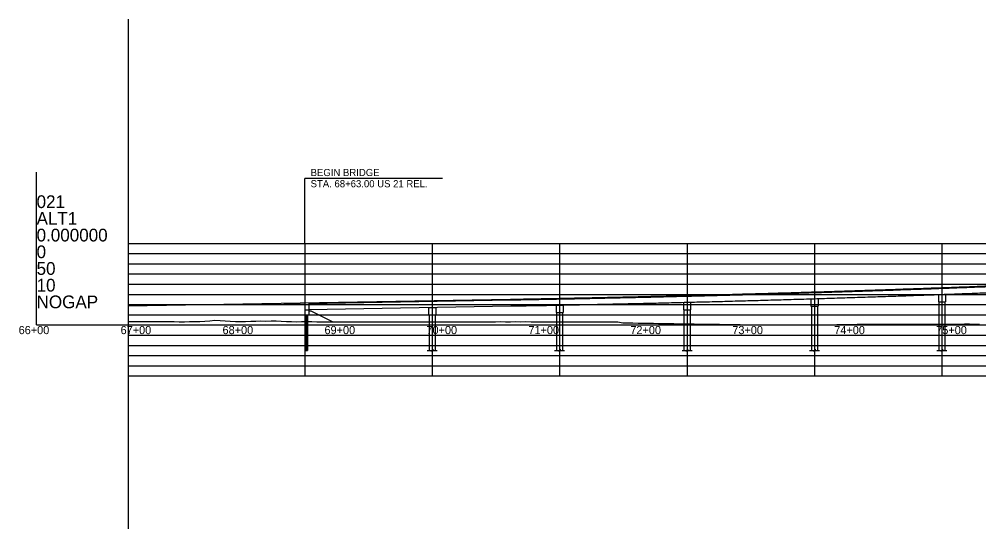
# Model space of a CAD drawing. Extents: x -464 to 4306, y -1372 to 300.
# Drawn here: x -187 to 754, y -200 to 300 of the extents above; entities that cross this region are included whole.
import ezdxf

# ---------------------------------------------------------------- set-up
doc = ezdxf.new("R2010")
doc.units = 0
for name, color, linetype in [('BR_AUTO DIMENSION', 7, 'Continuous'), ('BR_GRID LINES', 7, 'Continuous'), ('Default', 7, 'Continuous'), ('Mis Ground Lines', 7, 'Continuous'), ('Miscellaneous Lines', 7, 'Continuous'), ('NOPLOT', 7, 'Continuous'), ('sub interior bent cap lines', 7, 'Continuous'), ('Sub Interior Bent Footing Line', 7, 'Continuous'), ('Sub Steel Pile Lines', 7, 'Continuous'), ('Sup Concrete Girder Lines', 7, 'Continuous'), ('Sup Concrete Slab Lines', 7, 'Continuous')]:
    doc.layers.add(name, color=color, linetype=linetype)

msp = doc.modelspace()

# ---------------------------------------------------------------- linework, layer by layer
at = {"layer": 'BR_AUTO DIMENSION'}
for points in [[(93.81, -25), (94.51, -25), (94.51, -25.32), (94.83, -24.68), (94.83, -25), (95.53, -25)], [(212.8, -25), (217.11, -25), (217.11, -26.12), (218.23, -23.88), (218.23, -25), (222.55, -25)], [(337.8, -25), (342.11, -25), (342.11, -26.12), (343.23, -23.88), (343.23, -25), (347.55, -25)], [(462.8, -25), (467.11, -25), (467.11, -26.12), (468.23, -23.88), (468.23, -25), (472.55, -25)], [(587.8, -25), (592.11, -25), (592.11, -26.12), (593.23, -23.88), (593.23, -25), (597.55, -25)], [(712.8, -25), (717.11, -25), (717.11, -26.12), (718.23, -23.88), (718.23, -25), (722.55, -25)]]:
    msp.add_lwpolyline(points, dxfattribs=at)
at = {"layer": 'BR_GRID LINES'}
for p, q in [((-80.33, 300), (-80.33, -200)), ((-80.33, 80), (3939.67, 80)), ((-80.33, 70), (3939.67, 70)), ((-80.33, 60), (3939.67, 60)), ((-80.33, 50), (3939.67, 50)), ((-80.33, 40), (3939.67, 40)), ((-80.33, 30), (3939.67, 30)), ((-80.33, 20), (3939.67, 20)), ((-80.33, 10), (3939.67, 10)), ((-80.33, 0), (3939.67, 0)), ((-80.33, -10), (3939.67, -10)), ((-80.33, -20), (3939.67, -20)), ((-80.33, -30), (3939.67, -30)), ((-80.33, -40), (3939.67, -40)), ((-80.33, -50), (3939.67, -50))]:
    msp.add_line(p, q, dxfattribs=at)
at = {"layer": 'Default'}
for p, q in [((-170.33, 0), (-170.33, 150)), ((92.67, 80), (92.67, -50)), ((217.67, 80), (217.67, -50)), ((342.67, 80), (342.67, -50)), ((467.67, 80), (467.67, -50)), ((592.67, 80), (592.67, -50)), ((717.67, 80), (717.67, -50)), ((-170.33, 0), (4029.67, 0))]:
    msp.add_line(p, q, dxfattribs=at)
at = {"layer": 'Mis Ground Lines'}
for p, q in [((96.67, 13.81), (98.67, 13.81)), ((98.67, 13.81), (120.14, 3.08))]:
    msp.add_line(p, q, dxfattribs=at)
for points in [[(-80.33, 3.27), (-75.33, 3.48), (-70.33, 3.36)], [(-70.33, 3.36), (-65.33, 3.4), (-60.33, 3.4), (-55.33, 3.27), (-50.33, 3.54), (-45.33, 3.44), (-40.33, 3.45), (-35.33, 3.3), (-30.33, 3.21), (-25.33, 3.22), (-20.33, 3.29), (-15.33, 3.36), (-10.33, 3.53), (-5.33, 3.82), (-0.33, 4.21), (4.67, 4.56), (9.67, 4.44), (14.67, 4.05), (19.67, 3.77), (24.67, 3.53), (29.67, 3.47), (34.67, 3.49), (39.67, 3.75), (44.67, 3.69), (49.67, 3.93), (54.67, 3.85), (59.67, 3.92), (64.67, 3.93), (69.67, 3.82), (74.67, 3.52), (79.67, 3.35), (84.67, 3.13), (89.67, 3.26), (94.67, 3.36), (99.67, 3.33), (104.67, 3.19), (109.67, 3.19), (114.67, 3.15), (119.67, 3.07), (124.67, 3.11), (129.67, 3.14), (134.67, 3.07), (139.67, 3.23), (144.67, 3.17), (149.67, 3.08), (154.67, 3.1), (159.67, 3.12), (164.67, 3.11), (169.67, 3.1), (174.67, 3.1), (179.67, 3.08), (184.67, 3.07), (189.67, 3.17), (194.67, 3.12), (199.67, 3.1), (204.67, 3.11), (209.67, 3.08), (214.67, 3.11), (219.67, 3.13), (224.67, 3.09), (229.67, 3.11)], [(229.67, 3.11), (234.67, 3.14), (239.67, 3.21), (244.67, 3.19), (249.67, 3.13), (254.67, 3.12), (259.67, 3.15), (264.67, 3.19), (269.67, 3.23), (274.67, 3.21), (279.67, 3.18), (284.67, 3.27), (289.67, 3.23), (294.67, 3.22), (299.67, 3.32), (304.67, 3.18), (309.67, 3.34), (314.67, 3.1), (319.67, 3.23), (324.67, 3.2), (329.67, 3.13), (334.67, 3.15), (339.67, 3.09), (344.67, 3.08), (349.67, 3.21), (354.67, 3.22), (359.67, 3.13), (364.67, 3.07), (369.67, 3.13), (374.67, 3.12), (379.67, 3.07), (384.67, 3.18), (389.67, 3.11), (394.67, 3.16), (399.67, 3.17), (404.67, 2.05), (409.67, 2.03), (414.67, 1.95), (419.67, 1.87), (424.67, 1.79), (429.67, 1.71), (434.67, 1.63), (439.67, 1.55), (444.67, 1.48), (449.67, 1.4), (454.67, 1.32), (459.67, 1.24), (464.67, 1.16), (469.67, 1.08), (474.67, 1.01), (479.67, 0.93), (484.67, 0.85), (489.67, 0.77), (494.67, 0.69), (499.67, 0.62), (504.67, 0.54), (509.67, 0.46), (514.67, 0.38), (519.67, 0.3), (524.67, 0.23), (529.67, 0.15), (534.67, 0.16), (539.67, 0.16), (544.67, 0.17), (549.67, 0.18), (554.67, 0.16), (559.67, 0.14), (564.67, 0.12), (569.67, 0.1), (574.67, 0.13), (579.67, 0.11), (584.67, 0.09), (589.67, 0.09), (594.67, 0.07), (599.67, 0.14), (604.67, 0.21), (609.67, 0.28), (614.67, 0.35), (619.67, 0.41), (624.67, 0.48), (629.67, 0.55), (634.67, 0.62), (639.67, 0.69), (644.67, 0.76), (649.67, 0.79), (654.67, 0.79), (659.67, 0.79), (664.67, 0.78), (669.67, 0.77), (674.67, 0.76), (679.67, 0.75), (684.67, 0.72), (689.67, 0.73), (694.67, 0.74), (699.67, 0.76), (704.67, 0.75), (709.67, 0.75), (714.67, 0.79), (719.67, 0.83), (724.67, 0.87), (729.67, 0.9)], [(729.67, 0.9), (734.67, 0.94), (739.67, 0.95), (744.67, 0.95), (749.67, 0.94), (754.67, 0.93)]]:
    msp.add_lwpolyline(points, dxfattribs=at)
at = {"layer": 'Miscellaneous Lines'}
for p, q in [((72.67, 21.46), (72.67, 20.3)), ((72.67, 20.3), (92.67, 20.64))]:
    msp.add_line(p, q, dxfattribs=at)
at = {"layer": 'NOPLOT'}
for p in [(92.67, 143.85), (92.67, 80), (227.7, 143.85)]:
    msp.add_line(p, (92.67, 143.85), dxfattribs=at)
at = {"layer": 'sub interior bent cap lines'}
for p, q in [((721.17, 29.78), (714.17, 29.52)), ((714.17, 29.52), (714.17, 22.65)), ((721.17, 29.78), (721.17, 22.65)), ((346.17, 19.24), (339.17, 19.1)), ((339.17, 19.1), (339.17, 12.17)), ((346.17, 19.24), (346.17, 12.17)), ((471.17, 22.04), (464.17, 21.86)), ((464.17, 21.86), (464.17, 14.95)), ((471.17, 22.04), (471.17, 14.95)), ((596.17, 25.55), (589.17, 25.34)), ((589.17, 25.34), (589.17, 18.45)), ((596.17, 25.55), (596.17, 18.45)), ((714.17, 22.65), (721.17, 22.65)), ((714.67, 22.65), (714.67, -25)), ((720.67, 22.65), (720.67, -25)), ((214.17, 16.9), (221.17, 17.02)), ((214.17, 16.9), (214.17, 9.96)), ((214.17, 9.96), (221.17, 9.96)), ((214.67, 9.96), (214.67, -25)), ((220.67, 9.96), (220.67, -25)), ((221.17, 17.02), (221.17, 9.96)), ((339.17, 12.17), (346.17, 12.17)), ((339.67, 12.17), (339.67, -25)), ((345.67, 12.17), (345.67, -25)), ((464.17, 14.95), (471.17, 14.95)), ((464.67, 14.95), (464.67, -25)), ((470.67, 14.95), (470.67, -25)), ((589.17, 18.45), (596.17, 18.45)), ((589.67, 18.45), (589.67, -25)), ((595.67, 18.45), (595.67, -25))]:
    msp.add_line(p, q, dxfattribs=at)
at = {"layer": 'Sub Interior Bent Footing Line'}
for p, q in [((92.67, 21.81), (92.67, 9.81)), ((96.67, 21.88), (96.67, 9.81)), ((92.67, 14.81), (96.67, 14.81)), ((92.67, 9.81), (96.67, 9.81))]:
    msp.add_line(p, q, dxfattribs=at)
at = {"layer": 'Sub Steel Pile Lines'}
for p, q in [((94.06, 9.81), (94.06, -25)), ((95.28, 9.81), (95.28, -25))]:
    msp.add_line(p, q, dxfattribs=at)
at = {"layer": 'Sup Concrete Girder Lines'}
for p, q in [((96.67, 21.21), (294.68, 24.62)), ((96.67, 15.21), (294.79, 18.63))]:
    msp.add_line(p, q, dxfattribs=at)
for points in [[(294.68, 24.62), (304.68, 24.8), (314.68, 24.98), (324.68, 25.16), (334.68, 25.35), (344.68, 25.54), (354.69, 25.74), (364.69, 25.94), (374.69, 26.15), (384.69, 26.36), (394.69, 26.58), (404.69, 26.8), (414.69, 27.02), (424.69, 27.25), (434.69, 27.48), (444.69, 27.72), (454.69, 27.97), (464.69, 28.21), (474.69, 28.46), (484.69, 28.72), (494.69, 28.98), (504.69, 29.25), (514.69, 29.52), (524.69, 29.79), (534.69, 30.07), (544.69, 30.36), (554.69, 30.64), (564.69, 30.94), (574.69, 31.24), (584.69, 31.54), (594.69, 31.84), (604.69, 32.16), (614.69, 32.47), (624.69, 32.79), (634.69, 33.12), (644.69, 33.45), (654.69, 33.78), (664.69, 34.12), (674.69, 34.46), (684.7, 34.81), (694.7, 35.16), (704.7, 35.52), (714.7, 35.88), (724.7, 36.25), (734.7, 36.62), (744.7, 36.99), (754.7, 37.37), (764.7, 37.75), (774.7, 38.14), (784.7, 38.54), (794.7, 38.93)], [(294.79, 18.63), (304.79, 18.8), (314.79, 18.98), (324.8, 19.16), (334.8, 19.35), (344.8, 19.54), (354.8, 19.74), (364.81, 19.94), (374.81, 20.15), (384.81, 20.36), (394.82, 20.58), (404.82, 20.8), (414.82, 21.02), (424.83, 21.25), (434.83, 21.49), (444.83, 21.72), (454.84, 21.97), (464.84, 22.21), (474.84, 22.47), (484.84, 22.72), (494.85, 22.98), (504.85, 23.25), (514.85, 23.52), (524.86, 23.8), (534.86, 24.07), (544.86, 24.36), (554.87, 24.65), (564.87, 24.94), (574.87, 25.24), (584.87, 25.54), (594.88, 25.85), (604.88, 26.16), (614.88, 26.47), (624.89, 26.79), (634.89, 27.12), (644.89, 27.45), (654.9, 27.78), (664.9, 28.12), (674.9, 28.47), (684.9, 28.81), (694.91, 29.17), (704.91, 29.52), (714.91, 29.88), (724.92, 30.25), (734.92, 30.62), (744.92, 30.99), (754.93, 31.37), (764.93, 31.76), (774.93, 32.15), (784.94, 32.54), (794.94, 32.94)]]:
    msp.add_spline(points, degree=3, dxfattribs=at)
at = {"layer": 'Sup Concrete Slab Lines'}
msp.add_line((-80.33, 18.83), (294.67, 25.29), dxfattribs=at)
msp.add_spline([(294.67, 25.29), (304.67, 25.47), (314.67, 25.64), (324.67, 25.83), (334.67, 26.02), (344.67, 26.21), (354.67, 26.41), (364.67, 26.61), (374.67, 26.82), (384.67, 27.03), (394.67, 27.24), (404.67, 27.46), (414.67, 27.69), (424.67, 27.92), (434.67, 28.15), (444.67, 28.39), (454.67, 28.63), (464.67, 28.88), (474.67, 29.13), (484.67, 29.39), (494.67, 29.65), (504.67, 29.91), (514.67, 30.18), (524.67, 30.46), (534.67, 30.74), (544.67, 31.02), (554.67, 31.31), (564.67, 31.6), (574.67, 31.9), (584.67, 32.2), (594.67, 32.51), (604.67, 32.82), (614.67, 33.14), (624.67, 33.46), (634.67, 33.78), (644.67, 34.11), (654.67, 34.45), (664.67, 34.78), (674.67, 35.13), (684.67, 35.48), (694.67, 35.83), (704.67, 36.18), (714.67, 36.55), (724.67, 36.91), (734.67, 37.28), (744.67, 37.66), (754.67, 38.04), (764.67, 38.42), (774.67, 38.81), (784.67, 39.2), (794.67, 39.6)], degree=3, dxfattribs=at)

# ---------------------------------------------------------------- texts
at = {"layer": 'Default'}
for s, p in [('021', (-170.33, 114.7)), ('ALT1', (-170.33, 98.32)), ('0.000000', (-170.33, 81.93)), ('0', (-170.33, 65.55)), ('50', (-170.33, 49.16)), ('10', (-170.33, 32.77)), ('NOGAP', (-170.33, 16.39))]:
    msp.add_text(s, height=12.5, dxfattribs=at).set_placement(p)
at = {"layer": 'NOPLOT'}
for s, height, p in [('BEGIN BRIDGE', 7, (98.47, 146.08)), ('STA. 68+63.00 US 21 REL.', 7, (98.47, 135.08)), ('66+00', 8, (-187.92, -9)), ('67+00', 8, (-87.92, -9)), ('68+00', 8, (12.08, -9)), ('69+00', 8, (112.08, -9)), ('70+00', 8, (212.08, -9)), ('71+00', 8, (312.08, -9)), ('72+00', 8, (412.08, -9)), ('73+00', 8, (512.08, -9)), ('74+00', 8, (612.08, -9)), ('75+00', 8, (712.08, -9))]:
    msp.add_text(s, height=height, dxfattribs=at).set_placement(p)

doc.saveas('drawing.dxf')
